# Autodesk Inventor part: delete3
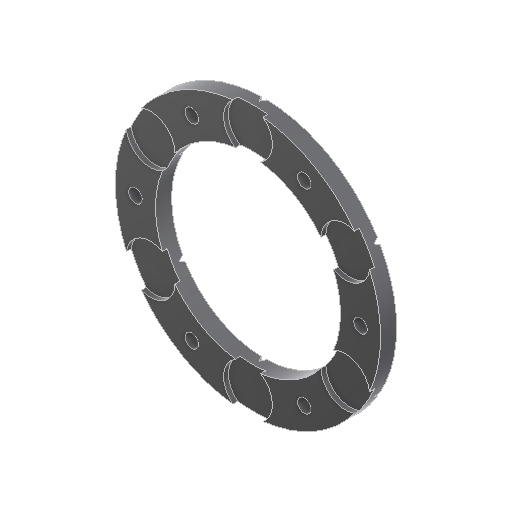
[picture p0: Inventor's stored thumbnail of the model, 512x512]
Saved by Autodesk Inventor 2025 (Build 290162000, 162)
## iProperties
Created: 2025-01
Part Number: delete3
Material: Thermoplastic Resin
Document SubType Name: Modeling
Designer: dansp
Density: 1.28 g/cm^3
Appearance: Smooth - Black
Mass: 15.0278 g
Surface Area: 81.5062 cm^2
Volume: 11.7404 cm^3
Author: dansp
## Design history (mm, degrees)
sketch "Sketch1"
  geometry: L1 (0, 57.75)-(0, -57.75) reference; L2 (-57.75, 0)-(57.75, 0) reference; C1 r 41.25 at (0, 0); C2 r 28.75 at (0, 0); 1 further point
  constraints: 2 centre point, 2 coincident
  dimensions: "d0" = 82.5 diameter of C1; "d1" = 12.5 radial gap between concentric circles of C1 C2
extrude "Extrusion1" new body sketch "Sketch1" distance "d2" = 5; taper "d3" = 0 deg
sketch "Sketch3" dims "d41" = 70 (= 0.5 x d40 + 0.5 x d39)
  geometry: C1 r 41.25 at (0, 0) reference; C2 r 28.75 at (0, 0) reference; C3 r 7.6 at (0, 35); 1 further point
  constraints: 2 vertical alignment, 1 centre point, 1 coincident, 2 other
  dimensions: "d39" = 82.5 diameter of C1 (derived); "d40" = 57.5 diameter of C2 (derived); "d42" = 15.2 diameter of C3
extrude "Extrusion3" cut sketch "Sketch3" distance "d16" = 1.5; taper "d17" = 0 deg
pattern_circular "Circular Pattern3" dims angle "d19" = 360 deg
sketch "Sketch5"
  geometry: L1 (-40.25, 0)-(40.25, 0) reference; L2 (0, -0.3)-(0, 1.8) reference; L3 (0.866, 0)-(0, 1.5); L4 (0, 1.5)-(-0.866, 0); L5 (-28.75, 0)-(28.75, 0) reference; 2 further points
  constraints: 4 end point, 3 point on line, 1 other
  dimensions: "d29" = 60 deg angle of L4 L3; "d30" = 1.5 distance from line of L3.end L1
extrude "Extrusion5" cut sketch "Sketch5" extent not by distance; stored distance "d31" = 0; taper "d32" = 0 deg
pattern_circular "Circular Pattern5" dims angle "d34" = 360 deg
sketch "Sketch8"
  geometry: L1 (-57.75, 0)-(57.75, 0) reference; L2 (0, -57.75)-(0, 57.75) reference; C1 r 2.1 at (35, 0); C2 r 2.1 at (-35, 0); A1 r 28.75 centre (0, 0) between (3.91, 28.483) and (-3.91, 28.483) reference; A2 r 7.6 centre (0, 35) between (-4.687, 40.983) and (-3.91, 28.483) reference; A3 r 41.25 centre (0, 0) between (4.687, 40.983) and (-4.687, 40.983) reference; A4 r 7.6 centre (0, 35) between (3.91, 28.483) and (4.687, 40.983) reference; A5 r 35 centre (0, 0) between (0, 35) and (35, 0); 1 further point
  constraints: 3 centre point, 2 point on circle, 1 coincident, 1 point on line, 1 symmetric about line, 1 other
  dimensions: "d44" = 4.2 diameter of C1
extrude "Extrusion6" cut sketch "Sketch8" extent not by distance; stored distance "d45" = 0; taper "d46" = 0 deg
pattern_circular "Circular Pattern7" dims angle "d51" = 360 deg
body "Solid1"
node "Projected Loop2"
node "Projected Loop6"
